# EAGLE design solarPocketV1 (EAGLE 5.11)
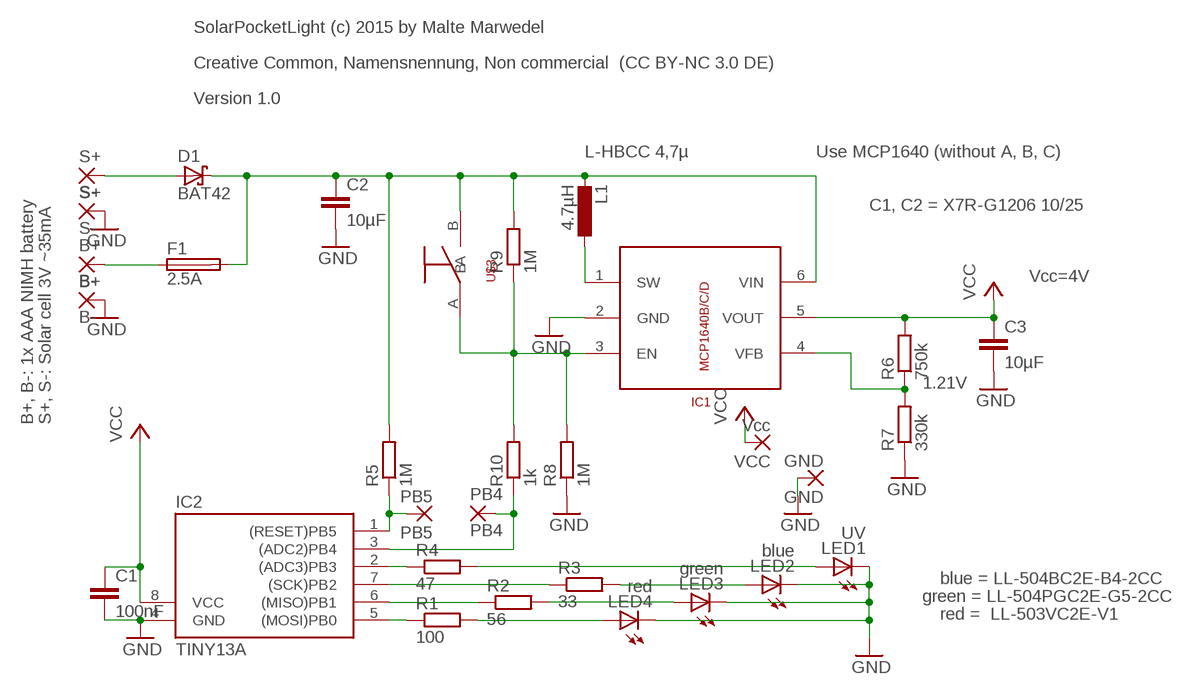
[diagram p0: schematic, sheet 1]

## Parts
B+  B+  1,6/0,8  [1,6/0,8]
B-  B-  1,6/0,8  [1,6/0,8]
C1  100nF  C-EUC0805  [C0805]
C2  10µF  C-EUC0805  [C0805]
C3  10µF  C-EUC0805  [C0805]
D1  BAT42  [DO35-10]
F1  2.5A  TR5  [TR5]
GND  GND  1,6/0,8  [1,6/0,8]
IC1  MCP1640  [SOT23-6]
IC2  TINY13A  TINY138P3  [DIL08]
L1  4.7µH  L-EU0207/15  [0207/15]
LED1  UV  LED5MM  [LED5MM]
LED2  blue  LED5MM  [LED5MM]
LED3  green  LED5MM  [LED5MM]
LED4  red  LED5MM  [LED5MM]
PB4  PB4  1,6/0,8  [1,6/0,8]
PB5  PB5  1,6/0,8  [1,6/0,8]
R1  100  R-EU_R0805  [R0805]
R2  56  R-EU_R0805  [R0805]
R3  33  R-EU_R0805  [R0805]
R4  47  R-EU_R0805  [R0805]
R5  1M  R-EU_R0805  [R0805]
R6  750k  R-EU_R0805  [R0805]
R7  330k  R-EU_R0805  [R0805]
R8  1M  R-EU_R0805  [R0805]
R9  1M  R-EU_R0805  [R0805]
R10  1k  R-EU_R0805  [R0805]
S+  S+  1,6/0,8  [1,6/0,8]
S-  S-  1,6/0,8  [1,6/0,8]
U$3  TASTER1082  [TASTER-MTG]
VCC  Vcc  1,6/0,8  [1,6/0,8]

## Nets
GND: B-.1(P) C1.2 C2.2 C3.2 GND.1(P) IC1.2(GND) IC2.4(GND) LED1.K(C) LED2.K(C) LED3.K(C) LED4.K(C) R7.1 R8.1 S-.1(P)
N$1: IC2.2((ADC3)PB3) R4.1
N$2: IC2.7((SCK)PB2) R3.1
N$3: IC2.6((MISO)PB1) R2.1
N$4: IC2.5((MOSI)PB0) R1.1
N$5: LED1.A R4.2
N$6: LED2.A R3.2
N$7: LED3.A R2.2
N$8: LED4.A R1.2
N$9: D1.A S+.1(P)
N$10: B+.1(P) F1.1
N$11: C2.1 D1.C F1.2 IC1.6(VIN) L1.2 R5.2 R9.2 U$3.B
N$12: IC1.3(EN) R8.2 R9.1 R10.2 U$3.A
N$13: IC2.3((ADC2)PB4) PB4.1(P) R10.1
N$14: IC1.1(SW) L1.1
N$15: IC1.4(VFB) R6.1 R7.2
N$16: IC2.1((RESET)PB5) PB5.1(P) R5.1
VCC: C1.1 C3.1 IC1.5(VOUT) IC2.8(VCC) R6.2 VCC.1(P)

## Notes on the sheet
- SolarPocketLight (c) 2015 by Malte Marwedel
- Creative Common, Namensnennung, Non commercial  (CC BY-NC 3.0 DE)
- Version 1.0
- L-HBCC 4,7µ | Use MCP1640 (without A, B, C)
- C1, C2 = X7R-G1206 10/25
- Vcc=4V
- 1.21V
- B+, B-: 1x AAA NIMH battery | S+, S-: Solar cell 3V ~35mA
- blue = LL-504BC2E-B4-2CC
- green = LL-504PGC2E-G5-2CC
- red =  LL-503VC2E-V1

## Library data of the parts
B+ B- GND PB4 PB5 S+ S- VCC = wirepad:1,6/0,8: THROUGH-HOLE PAD
C1-C3 = rcl:C-EU: CAPACITOR, European symbol
D1 = diode:BAT42: DIODE
F1 = fuse:TR5: FUSE; OC_FARNELL: unknown; OC_NEWARK: unknown
IC1 = maltes2_lib:MCP1640: Boost Regulator 0.65V Start-up Synchronous Boost Regulator VFB=1.21V FB bias current 10pA Typical: Cin = 4.7µF Cout = 10µF L=4.7µH
IC2 = avr-7:TINY13*
L1 = rcl:L-EU: INDUCTOR, European symbol
LED1-LED4 = led:LED: LED
R1-R10 = rcl:R-EU_: RESISTOR, European symbol
U$3 = maltes_lib:TASTER1082: Taster

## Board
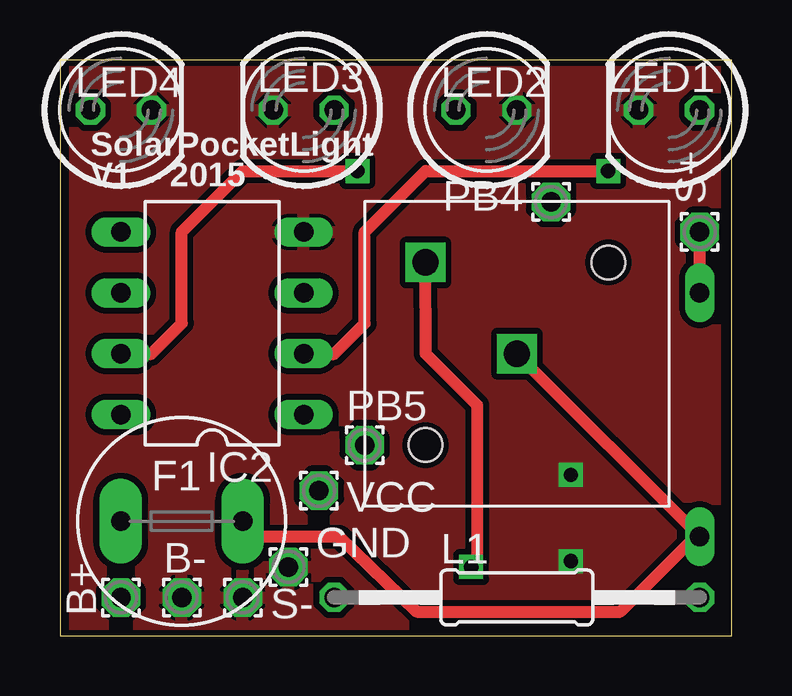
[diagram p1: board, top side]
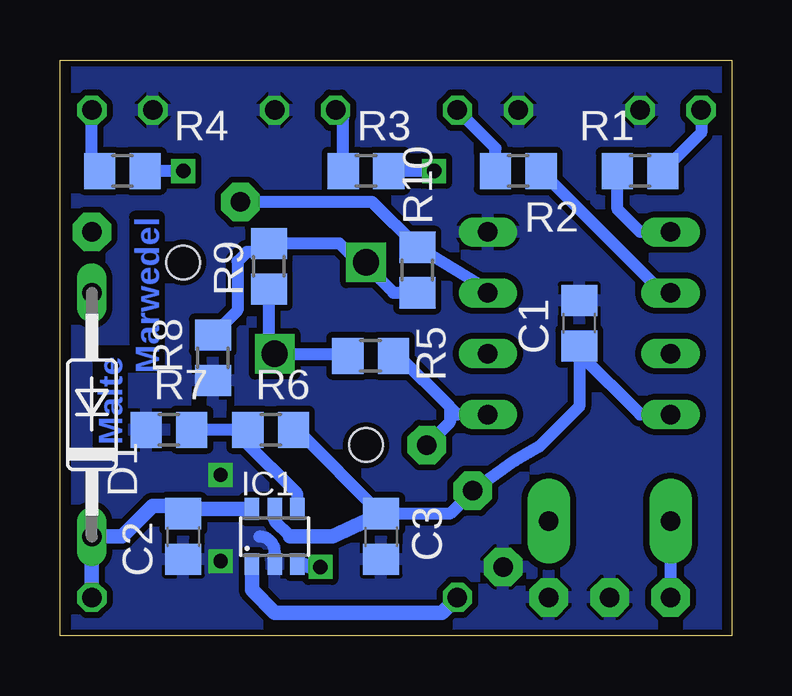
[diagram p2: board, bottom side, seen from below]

Size 28 x 24 mm. Coordinates in mm from the lower left corner, seen from the top.
Outline: 0,0 28,0 28,24 0,24 0,0
Copper layers (1*16): Top 0.035mm / dielectric 1.5mm / Bottom 0.035mm
Design rules "platinensammler_02": minimum track width 0.15mm, minimum drill 0.3mm, track to track 0.15mm, track to pad 0.15mm, pad to pad 0.15mm, via to via 0.15mm, smd to smd 0mil, copper to edge 0.2mm, drill to drill 0.2mm, minimum pad ring 0.2mm, minimum via ring 0.2mm, stop-mask expansion 4mil, vias tented up to drill 0.8mm, thermal gap 0.15mm

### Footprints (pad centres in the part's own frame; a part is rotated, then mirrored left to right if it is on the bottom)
1,6/0,8 = drill 0.813 pad 1.6 octagon: 1 0,0
C0805 = smd 1.3 x 1.5: 1 -0.95,0; 2 0.95,0
DO35-10 = drill 0.813 long: A 5.08,0; C -5.08,0
TR5 = drill 0.813 pad 1.778 long: 1 -2.54,0; 2 2.54,0
SOT23-6 = smd 0.6 x 0.9: 1 -0.95,-1.15; 2 0,-1.15; 3 0.95,-1.15; 4 0.95,1.15; 5 0,1.15; 6 -0.95,1.15
DIL08 = drill 0.813 long: 1 -3.81,-3.81; 2 -1.27,-3.81; 3 1.27,-3.81; 4 3.81,-3.81; 5 3.81,3.81; 6 1.27,3.81; 7 -1.27,3.81; 8 -3.81,3.81
0207/15 = drill 0.813 octagon: 1 -7.62,0; 2 7.62,0
LED5MM = drill 0.813 octagon: A -1.27,0; K 1.27,0
R0805 = smd 1.3 x 1.5: 1 -0.95,0; 2 0.95,0
TASTER-MTG = drill 1.1 square: A -3.81,3.81; B 0,0 | hole 1.4: -3.81,-3.81; 3.81,3.81

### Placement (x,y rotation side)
B+  2.54,1.59 0 top
B-  5.08,1.59 0 top
C1  6.35,13.02 90 bottom
C2  22.86,4.13 270 bottom
C3  14.61,4.13 270 bottom
D1  26.67,9.21 90 bottom
F1  5.08,4.77 0 top
GND  9.53,2.86 0 top
IC1  19.05,4.13 0 bottom
IC2  6.35,13.02 90 top
L1  19.05,1.59 0 top
LED1  25.4,21.91 180 top
LED2  17.78,21.91 0 top
LED3  10.16,21.91 180 top
LED4  2.54,21.91 0 top
PB4  20.48,18.08 90 top
PB5  12.7,7.94 0 top
R1  3.81,19.37 0 bottom
R2  8.89,19.37 180 bottom
R3  15.24,19.37 180 bottom
R4  25.4,19.37 180 bottom
R5  15.05,11.66 180 bottom
R6  19.21,8.57 0 bottom
R7  23.46,8.57 0 bottom
R8  21.62,11.59 90 bottom
R9  19.29,15.4 270 bottom
R10  13.1,15.24 270 bottom
S+  26.67,16.83 0 top
S-  7.62,1.59 0 top
U$3  19.05,11.75 0 top
VCC  10.79,6.04 0 top

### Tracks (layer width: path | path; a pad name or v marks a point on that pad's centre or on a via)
GND  (via drill 0.6)
  Bottom 0.5: IC1.2 19.05,3.5 arc-90 19.68,4.13
  other vias: 21.3,6.7 21.3,3.1
  pour Bottom (isolate 0.254): 0.64,23.81 27.3,23.81 27.3,-0.95 0.64,-0.95 0.64,21.91
  pour Top (isolate 0.254): 0.64,23.81 27.3,23.81 27.3,-0.95 0.64,-0.95 0.64,22.55
N$1  (via drill 0.6)
  Top 0.5: v22.86,19.37 15.24,19.37 12.7,16.83 12.7,13.02 11.43,11.75 IC2.2
  Bottom 0.5: v22.86,19.37 R4.1
N$2  (via drill 0.6)
  Top 0.5: v12.4,19.37 7.62,19.37 5.08,16.83 5.08,13.02 3.81,11.75 IC2.7
  Bottom 0.5: v12.4,19.37 R3.1
N$3
  Bottom 0.5: R2.1 2.86,14.29 IC2.6
N$4
  Bottom 0.5: IC2.5 3.81,16.83 4.76,17.78 R1.1
N$5
  Bottom 0.5: R4.2 26.67,19.69 LED1.A
N$6
  Bottom 0.5: LED2.A 16.19,21.59 R3.2
N$7
  Bottom 0.5: R2.2 9.84,20.32 LED3.A
N$8
  Bottom 0.5: LED4.A 1.27,20.96 R1.2
N$9
  Top 0.5: D1.A S+.1
N$10
  Bottom 0.5: B+.1 F1.1
N$11
  Top 0.5: F1.2 8.26,4.13 11.63,4.13 14.88,0.99 23.36,0.99 26.5,4.13 D1.C U$3.B
  Bottom 0.5: 22.99,5.4 C2.1 22.86,5.28 | R9.2 19.29,11.98 U$3.B 16.09,11.75 R5.2
  Bottom 0.6: L1.2 D1.C 25.4,4.13 24.13,5.4 22.99,5.4 | 22.86,5.28 IC1.6
N$12  (via drill 0.6)
  Top 0.5: U$3.A 15.25,11.75 17.4,9.6 17.4,3.11 v17.14,2.86
  Bottom 0.406: R8.2 22.07,12.73 | R9.1 19.63,16
  Bottom 0.5: IC1.3 17.78,2.98 17.66,2.86 v17.14,2.86 | 19.63,16 20.2,16 20.6,15.6 20.6,13.56 R8.2 | R9.1 16.34,16.34 15.8,15.8 15.48,15.8 U$3.A 15.24,15.44 14.1,14.3 R10.2
N$13
  Bottom 0.5: IC2.3 10.48,14.61 R10.1 14.99,18.08 PB4.1
N$14
  Bottom 0.6: IC1.1 20,1.91 19.05,0.95 12.06,0.95 L1.1
N$15
  Bottom 0.5: R7.2 R6.1 20.36,8.16 18.1,5.9 IC1.4
N$16
  Bottom 0.5: IC2.1 11.43,9.21 11.75,9.53 | PB5.1 11.75,8.89 11.75,9.53 | 11.75,9.53 13.88,11.66 R5.1
VCC
  Bottom 0.5: IC2.8 3.81,9.21 6.35,11.75 | 6.35,11.75 C1.1 | IC1.5 19.05,4.77 18.41,4.13 | R6.2 18.1,8.57 C3.1 11.75,5.08 VCC.1 9.03,7.3 8,7.9 6.35,9.55 6.35,11.75
  Bottom 0.6: 18.41,4.13 16.64,4.13 C3.1

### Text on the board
Bottom: Marwedel | Malte
tNames: SolarPocketLight | V1 2015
